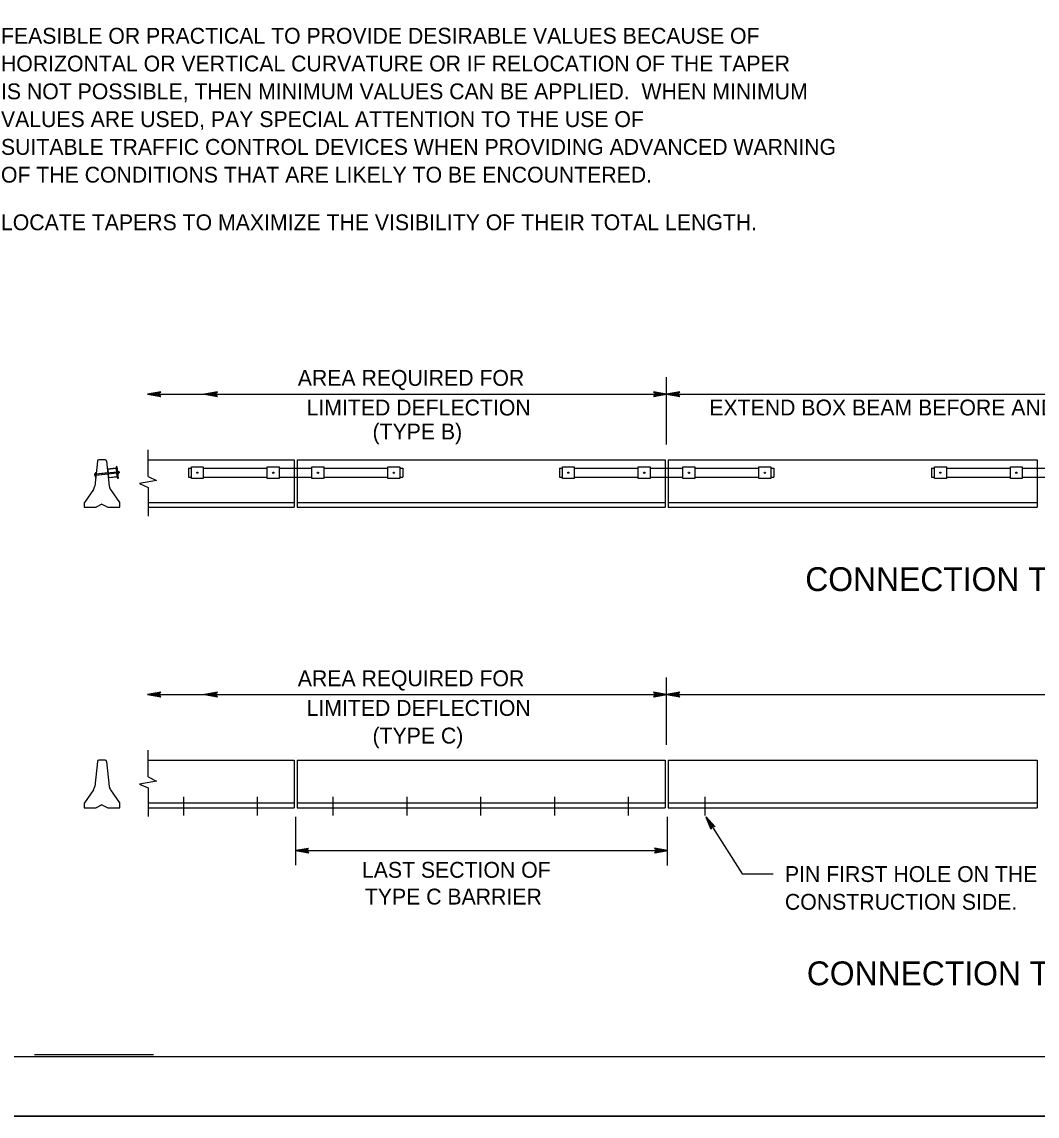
# Model space of a CAD drawing. Extents: x 499909 to 500993, y 502505 to 503165.
# Drawn here: x 500041.5 to 500297.3, y 502505 to 502780.7 of the extents above; entities that cross this region are included whole.
import ezdxf

# ---------------------------------------------------------------- set-up
doc = ezdxf.new("R2010")
doc.units = 0
for name, color, linetype in [('1', 7, 'Continuous'), ('24', 7, 'Continuous'), ('3', 7, 'Continuous'), ('41', 7, 'Continuous'), ('5', 7, 'Continuous')]:
    doc.layers.add(name, color=color, linetype=linetype)

msp = doc.modelspace()

# ---------------------------------------------------------------- linework, layer by layer
at = {"layer": '1'}
for p, q in [((500000, 502520), (500990, 502520)), ((500074.65, 502520.47), (500044.67, 502520.47)), ((500993, 502505), (499944.83, 502505))]:
    msp.add_line(p, q, dxfattribs=at)
at = {"layer": '24'}
for points in [[(500073.16, 502686.89), (500076.48, 502686.3), (500075.69, 502686.89), (500076.46, 502687.47), (500073.16, 502686.89), (500073.38, 502686.9), (500076.39, 502686.34), (500075.63, 502686.9), (500076.33, 502687.42), (500073.5, 502686.91), (500073.61, 502686.89), (500076.19, 502686.43), (500075.61, 502686.9), (500076.2, 502687.35), (500073.66, 502686.89), (500073.77, 502686.91), (500076.02, 502686.5), (500075.59, 502686.89), (500076.03, 502687.29), (500074.09, 502686.91), (500074.28, 502686.91), (500075.86, 502686.58), (500075.55, 502686.88), (500075.88, 502687.21), (500074.31, 502686.89), (500074.49, 502686.88), (500075.68, 502686.68), (500075.45, 502686.91), (500075.69, 502687.13), (500074.65, 502686.89), (500074.82, 502686.87), (500075.53, 502686.74), (500075.41, 502686.9), (500075.61, 502687.07), (500074.91, 502686.89), (500075.37, 502686.78), (500075.3, 502686.91), (500075.51, 502687.03), (500075.02, 502686.91), (500075.33, 502686.83), (500075.2, 502686.93), (500075.35, 502686.99), (500075.2, 502686.9), (500075.28, 502686.88)], [(500087.47, 502686.89), (500090.79, 502686.3), (500090, 502686.89), (500090.77, 502687.47), (500087.47, 502686.89), (500087.69, 502686.9), (500090.7, 502686.34), (500089.93, 502686.9), (500090.64, 502687.42), (500087.8, 502686.91), (500087.92, 502686.89), (500090.49, 502686.43), (500089.92, 502686.9), (500090.51, 502687.35), (500087.97, 502686.89), (500088.08, 502686.91), (500090.33, 502686.5), (500089.89, 502686.89), (500090.34, 502687.29), (500088.4, 502686.91), (500088.59, 502686.91), (500090.16, 502686.58), (500089.86, 502686.88), (500090.19, 502687.21), (500088.62, 502686.89), (500088.8, 502686.88), (500089.98, 502686.68), (500089.76, 502686.91), (500090, 502687.13), (500088.96, 502686.89), (500089.13, 502686.87), (500089.84, 502686.74), (500089.72, 502686.9), (500089.92, 502687.07), (500089.21, 502686.89), (500089.68, 502686.78), (500089.61, 502686.91), (500089.82, 502687.03), (500089.33, 502686.91), (500089.64, 502686.83), (500089.51, 502686.93), (500089.65, 502686.99), (500089.51, 502686.9), (500089.58, 502686.88)], [(500203.94, 502686.89), (500200.62, 502687.48), (500201.41, 502686.89), (500200.63, 502686.31), (500203.94, 502686.89), (500203.72, 502686.88), (500200.71, 502687.43), (500201.47, 502686.88), (500200.77, 502686.36), (500203.6, 502686.87), (500203.49, 502686.89), (500200.91, 502687.35), (500201.49, 502686.88), (500200.89, 502686.43), (500203.44, 502686.89), (500203.33, 502686.87), (500201.07, 502687.28), (500201.51, 502686.89), (500201.07, 502686.48), (500203.01, 502686.87), (500202.82, 502686.87), (500201.24, 502687.2), (500201.55, 502686.9), (500201.22, 502686.57), (500202.79, 502686.89), (500202.61, 502686.9), (500201.42, 502687.1), (500201.65, 502686.87), (500201.4, 502686.64), (500202.45, 502686.89), (500202.28, 502686.91), (500201.57, 502687.04), (500201.68, 502686.88), (500201.49, 502686.7), (500202.19, 502686.89), (500201.73, 502687), (500201.79, 502686.87), (500201.59, 502686.75), (500202.08, 502686.87), (500201.77, 502686.95), (500201.9, 502686.85), (500201.75, 502686.79), (500201.9, 502686.88), (500201.82, 502686.9)], [(500203.94, 502686.89), (500207.26, 502686.3), (500206.47, 502686.89), (500207.25, 502687.47), (500203.94, 502686.89), (500204.16, 502686.9), (500207.17, 502686.34), (500206.41, 502686.9), (500207.11, 502687.42), (500204.28, 502686.91), (500204.39, 502686.89), (500206.97, 502686.43), (500206.39, 502686.9), (500206.99, 502687.35), (500204.44, 502686.89), (500204.55, 502686.91), (500206.81, 502686.5), (500206.37, 502686.89), (500206.82, 502687.29), (500204.87, 502686.91), (500205.06, 502686.91), (500206.64, 502686.58), (500206.33, 502686.88), (500206.66, 502687.21), (500205.09, 502686.89), (500205.27, 502686.88), (500206.46, 502686.68), (500206.23, 502686.91), (500206.48, 502687.13), (500205.43, 502686.89), (500205.6, 502686.87), (500206.31, 502686.74), (500206.2, 502686.9), (500206.39, 502687.07), (500205.69, 502686.89), (500206.15, 502686.78), (500206.09, 502686.91), (500206.29, 502687.03), (500205.81, 502686.91), (500206.11, 502686.83), (500205.98, 502686.93), (500206.13, 502686.99), (500205.98, 502686.9), (500206.06, 502686.88)], [(500073.16, 502611.2), (500076.48, 502610.61), (500075.69, 502611.2), (500076.46, 502611.78), (500073.16, 502611.2), (500073.38, 502611.21), (500076.39, 502610.66), (500075.63, 502611.21), (500076.33, 502611.73), (500073.5, 502611.22), (500073.61, 502611.2), (500076.19, 502610.74), (500075.61, 502611.21), (500076.2, 502611.66), (500073.66, 502611.2), (500073.77, 502611.22), (500076.02, 502610.81), (500075.59, 502611.2), (500076.03, 502611.61), (500074.09, 502611.22), (500074.28, 502611.22), (500075.86, 502610.89), (500075.55, 502611.19), (500075.88, 502611.52), (500074.31, 502611.2), (500074.49, 502611.19), (500075.68, 502610.99), (500075.45, 502611.22), (500075.69, 502611.44), (500074.65, 502611.2), (500074.82, 502611.18), (500075.53, 502611.05), (500075.41, 502611.21), (500075.61, 502611.38), (500074.91, 502611.2), (500075.37, 502611.09), (500075.3, 502611.22), (500075.51, 502611.34), (500075.02, 502611.22), (500075.33, 502611.14), (500075.2, 502611.24), (500075.35, 502611.3), (500075.2, 502611.21), (500075.28, 502611.19)], [(500087.47, 502611.2), (500090.79, 502610.61), (500090, 502611.2), (500090.77, 502611.78), (500087.47, 502611.2), (500087.69, 502611.21), (500090.7, 502610.66), (500089.93, 502611.21), (500090.64, 502611.73), (500087.8, 502611.22), (500087.92, 502611.2), (500090.49, 502610.74), (500089.92, 502611.21), (500090.51, 502611.66), (500087.97, 502611.2), (500088.08, 502611.22), (500090.33, 502610.81), (500089.89, 502611.2), (500090.34, 502611.61), (500088.4, 502611.22), (500088.59, 502611.22), (500090.16, 502610.89), (500089.86, 502611.19), (500090.19, 502611.52), (500088.62, 502611.2), (500088.8, 502611.19), (500089.98, 502610.99), (500089.76, 502611.22), (500090, 502611.44), (500088.96, 502611.2), (500089.13, 502611.18), (500089.84, 502611.05), (500089.72, 502611.21), (500089.92, 502611.38), (500089.21, 502611.2), (500089.68, 502611.09), (500089.61, 502611.22), (500089.82, 502611.34), (500089.33, 502611.22), (500089.64, 502611.14), (500089.51, 502611.24), (500089.65, 502611.3), (500089.51, 502611.21), (500089.58, 502611.19)], [(500203.94, 502611.2), (500200.62, 502611.79), (500201.41, 502611.2), (500200.63, 502610.62), (500203.94, 502611.2), (500203.72, 502611.19), (500200.71, 502611.74), (500201.47, 502611.19), (500200.77, 502610.67), (500203.6, 502611.18), (500203.49, 502611.2), (500200.91, 502611.66), (500201.49, 502611.19), (500200.89, 502610.74), (500203.44, 502611.2), (500203.33, 502611.18), (500201.07, 502611.59), (500201.51, 502611.2), (500201.07, 502610.8), (500203.01, 502611.18), (500202.82, 502611.18), (500201.24, 502611.51), (500201.55, 502611.21), (500201.22, 502610.88), (500202.79, 502611.2), (500202.61, 502611.21), (500201.42, 502611.41), (500201.65, 502611.18), (500201.4, 502610.96), (500202.45, 502611.2), (500202.28, 502611.22), (500201.57, 502611.35), (500201.68, 502611.19), (500201.49, 502611.02), (500202.19, 502611.2), (500201.73, 502611.31), (500201.79, 502611.18), (500201.59, 502611.06), (500202.08, 502611.18), (500201.77, 502611.26), (500201.9, 502611.16), (500201.75, 502611.1), (500201.9, 502611.19), (500201.82, 502611.21)], [(500203.94, 502611.2), (500207.26, 502610.61), (500206.47, 502611.2), (500207.25, 502611.78), (500203.94, 502611.2), (500204.16, 502611.21), (500207.17, 502610.66), (500206.41, 502611.21), (500207.11, 502611.73), (500204.28, 502611.22), (500204.39, 502611.2), (500206.97, 502610.74), (500206.39, 502611.21), (500206.99, 502611.66), (500204.44, 502611.2), (500204.55, 502611.22), (500206.81, 502610.81), (500206.37, 502611.2), (500206.82, 502611.61), (500204.87, 502611.22), (500205.06, 502611.22), (500206.64, 502610.89), (500206.33, 502611.19), (500206.66, 502611.52), (500205.09, 502611.2), (500205.27, 502611.19), (500206.46, 502610.99), (500206.23, 502611.22), (500206.48, 502611.44), (500205.43, 502611.2), (500205.6, 502611.18), (500206.31, 502611.05), (500206.2, 502611.21), (500206.39, 502611.38), (500205.69, 502611.2), (500206.15, 502611.09), (500206.09, 502611.22), (500206.29, 502611.34), (500205.81, 502611.22), (500206.11, 502611.14), (500205.98, 502611.24), (500206.13, 502611.3), (500205.98, 502611.21), (500206.06, 502611.19)], [(500213.86, 502580.38), (500216.13, 502577.9), (500215.21, 502578.25), (500215.14, 502577.28), (500213.86, 502580.38), (500213.97, 502580.2), (500216.05, 502577.95), (500215.17, 502578.3), (500215.11, 502577.42), (500214.02, 502580.09), (500214.1, 502580), (500215.87, 502578.07), (500215.17, 502578.31), (500215.1, 502577.57), (500214.13, 502579.96), (500214.17, 502579.86), (500215.72, 502578.18), (500215.16, 502578.34), (500215.06, 502577.74), (500214.34, 502579.59), (500214.44, 502579.43), (500215.56, 502578.27), (500215.15, 502578.37), (500215.05, 502577.92), (500214.47, 502579.41), (500214.58, 502579.27), (500215.39, 502578.37), (500215.07, 502578.44), (500215.01, 502578.11), (500214.66, 502579.12), (500214.76, 502578.99), (500215.26, 502578.46), (500215.06, 502578.48), (500215.02, 502578.22), (500214.79, 502578.91), (500215.14, 502578.58), (500214.99, 502578.56), (500215, 502578.32), (500214.84, 502578.8), (500215.07, 502578.59), (500214.92, 502578.64), (500214.95, 502578.48), (500214.95, 502578.66), (500215, 502578.6)], [(500110.41, 502571.89), (500113.74, 502571.3), (500112.94, 502571.89), (500113.72, 502572.47), (500110.41, 502571.89), (500110.63, 502571.9), (500113.64, 502571.35), (500112.88, 502571.9), (500113.58, 502572.42), (500110.75, 502571.91), (500110.86, 502571.89), (500113.44, 502571.43), (500112.86, 502571.9), (500113.46, 502572.35), (500110.91, 502571.89), (500111.02, 502571.91), (500113.28, 502571.5), (500112.84, 502571.89), (500113.29, 502572.3), (500111.34, 502571.91), (500111.53, 502571.91), (500113.11, 502571.58), (500112.8, 502571.88), (500113.13, 502572.21), (500111.57, 502571.89), (500111.74, 502571.88), (500112.93, 502571.68), (500112.7, 502571.91), (500112.95, 502572.14), (500111.91, 502571.89), (500112.07, 502571.87), (500112.79, 502571.74), (500112.67, 502571.9), (500112.86, 502572.08), (500112.16, 502571.89), (500112.63, 502571.78), (500112.56, 502571.91), (500112.76, 502572.03), (500112.28, 502571.91), (500112.58, 502571.83), (500112.45, 502571.93), (500112.6, 502571.99), (500112.46, 502571.9), (500112.53, 502571.88)], [(500204.19, 502571.89), (500200.87, 502572.48), (500201.66, 502571.89), (500200.89, 502571.31), (500204.19, 502571.89), (500203.97, 502571.88), (500200.96, 502572.43), (500201.72, 502571.88), (500201.02, 502571.36), (500203.85, 502571.87), (500203.74, 502571.89), (500201.16, 502572.35), (500201.74, 502571.88), (500201.15, 502571.43), (500203.69, 502571.89), (500203.58, 502571.87), (500201.33, 502572.28), (500201.77, 502571.89), (500201.32, 502571.49), (500203.26, 502571.87), (500203.07, 502571.87), (500201.49, 502572.2), (500201.8, 502571.9), (500201.47, 502571.57), (500203.04, 502571.89), (500202.86, 502571.9), (500201.67, 502572.1), (500201.9, 502571.87), (500201.66, 502571.65), (500202.7, 502571.89), (500202.53, 502571.91), (500201.82, 502572.04), (500201.94, 502571.88), (500201.74, 502571.71), (500202.44, 502571.89), (500201.98, 502572), (500202.05, 502571.87), (500201.84, 502571.75), (500202.33, 502571.87), (500202.02, 502571.95), (500202.15, 502571.85), (500202, 502571.79), (500202.15, 502571.88), (500202.07, 502571.9)]]:
    msp.add_lwpolyline(points, dxfattribs=at)
at = {"layer": '3'}
for p, q in [((500073.16, 502686.89), (500765.89, 502686.89)), ((500073.26, 502666.2), (500073.26, 502672.89)), ((500060.5, 502670.06), (500059.84, 502663.75)), ((500062.44, 502670.39), (500060.87, 502670.39)), ((500062.82, 502670.06), (500063.48, 502663.75)), ((500073.26, 502670.39), (500110.06, 502670.39)), ((500110.06, 502670.39), (500110.06, 502668.24)), ((500110.82, 502670.39), (500110.82, 502668.24)), ((500110.82, 502670.39), (500203.54, 502670.39)), ((500203.54, 502670.39), (500203.54, 502668.24)), ((500204.29, 502670.39), (500204.29, 502668.24)), ((500204.29, 502670.39), (500297.28, 502670.39)), ((500297.28, 502670.39), (500297.28, 502668.24)), ((500059.87, 502666.9), (500059.94, 502666.23)), ((500060, 502666.71), (500059.89, 502666.7)), ((500059.97, 502666.42), (500059.92, 502666.42)), ((500060.05, 502667.16), (500059.93, 502666.04)), ((500059.93, 502666.04), (500060.07, 502666.02)), ((500065.59, 502667.01), (500059.97, 502666.42)), ((500059.98, 502666.43), (500060.12, 502666.42)), ((500065.56, 502667.29), (500060, 502666.71)), ((500060.01, 502666.76), (500060.15, 502666.74)), ((500060.05, 502667.16), (500060.19, 502667.14)), ((500063.17, 502666.73), (500060.12, 502666.41)), ((500063.13, 502667.06), (500060.15, 502666.75)), ((500063.04, 502667.92), (500063.26, 502665.87)), ((500063.11, 502667.91), (500063.32, 502665.9)), ((500065.18, 502668.24), (500063.12, 502668.03)), ((500065.16, 502668.17), (500063.16, 502667.96)), ((500065.41, 502666), (500063.36, 502665.79)), ((500065.38, 502666.07), (500063.38, 502665.86)), ((500065.21, 502668.13), (500065.42, 502666.12)), ((500065.42, 502668.64), (500065.23, 502668.62)), ((500065.23, 502668.62), (500065.54, 502665.64)), ((500065.42, 502668.64), (500065.73, 502665.66)), ((500065.75, 502667.45), (500065.57, 502667.43)), ((500065.77, 502667.31), (500065.58, 502667.29)), ((500065.8, 502667.03), (500065.61, 502667.01)), ((500065.81, 502666.89), (500065.63, 502666.87)), ((500065.78, 502667.39), (500065.83, 502666.97)), ((500065.98, 502667.34), (500065.79, 502667.32)), ((500066.01, 502667.06), (500065.82, 502667.04)), ((500065.84, 502667.28), (500065.86, 502667.09)), ((500065.89, 502667.33), (500065.91, 502667.05)), ((500065.94, 502667.28), (500065.96, 502667.1)), ((500065.98, 502667.34), (500066.01, 502667.06)), ((500073.26, 502666.2), (500075.37, 502665.12)), ((500083.44, 502668.24), (500083.44, 502665.99)), ((500083.44, 502668.24), (500084.19, 502668.24)), ((500083.44, 502665.99), (500084.19, 502665.99)), ((500087.19, 502668.24), (500103.32, 502668.24)), ((500087.19, 502665.99), (500103.32, 502665.99)), ((500106.31, 502668.24), (500114.57, 502668.24)), ((500106.31, 502665.99), (500114.57, 502665.99)), ((500110.06, 502668.23), (500110.06, 502666)), ((500110.06, 502666), (500110.06, 502658.4)), ((500110.82, 502668.23), (500110.82, 502666)), ((500110.82, 502665.99), (500110.82, 502658.4)), ((500117.56, 502668.24), (500133.69, 502668.24)), ((500117.56, 502665.99), (500133.69, 502665.99)), ((500136.69, 502668.24), (500137.44, 502668.24)), ((500136.69, 502665.99), (500137.44, 502665.99)), ((500137.44, 502668.24), (500137.44, 502665.99)), ((500176.92, 502668.24), (500176.92, 502665.99)), ((500176.92, 502668.24), (500177.67, 502668.24)), ((500176.92, 502665.99), (500177.67, 502665.99)), ((500180.67, 502668.24), (500196.79, 502668.24)), ((500180.67, 502665.99), (500196.79, 502665.99)), ((500199.79, 502668.24), (500208.04, 502668.24)), ((500199.79, 502665.99), (500208.04, 502665.99)), ((500203.54, 502668.23), (500203.54, 502666)), ((500203.54, 502665.99), (500203.54, 502658.4)), ((500204.29, 502668.23), (500204.29, 502666)), ((500204.29, 502668.23), (500204.29, 502666)), ((500204.29, 502665.99), (500204.29, 502658.4)), ((500211.04, 502668.24), (500227.17, 502668.24)), ((500211.04, 502665.99), (500227.17, 502665.99)), ((500230.17, 502668.24), (500230.92, 502668.24)), ((500230.17, 502665.99), (500230.92, 502665.99)), ((500230.92, 502668.24), (500230.92, 502665.99)), ((500270.66, 502668.24), (500270.66, 502665.99)), ((500270.66, 502668.24), (500271.41, 502668.24)), ((500270.66, 502665.99), (500271.41, 502665.99)), ((500274.41, 502668.24), (500290.54, 502668.24)), ((500274.41, 502665.99), (500290.54, 502665.99)), ((500293.54, 502668.24), (500301.79, 502668.24)), ((500293.54, 502665.99), (500301.79, 502665.99)), ((500297.28, 502668.23), (500297.28, 502665.99)), ((500297.28, 502665.99), (500297.28, 502658.4)), ((500065.73, 502665.66), (500065.54, 502665.64)), ((500075.37, 502665.12), (500071.12, 502664.36)), ((500071.12, 502664.36), (500073.26, 502663.41)), ((500073.26, 502663.41), (500073.26, 502656.15)), ((500059.51, 502662.87), (500057.23, 502659.62)), ((500063.81, 502662.87), (500066.09, 502659.62)), ((500057.16, 502659.4), (500057.16, 502658.4)), ((500057.16, 502658.4), (500060.16, 502658.4)), ((500061.66, 502659.15), (500060.16, 502658.4)), ((500061.66, 502659.15), (500063.16, 502658.4)), ((500063.16, 502658.4), (500066.16, 502658.4)), ((500066.16, 502658.4), (500066.16, 502659.4)), ((500073.26, 502659.62), (500110.06, 502659.62)), ((500073.26, 502658.4), (500110.06, 502658.4)), ((500110.79, 502659.62), (500203.54, 502659.62)), ((500110.82, 502658.4), (500203.54, 502658.4)), ((500204.26, 502659.62), (500297.28, 502659.62)), ((500204.29, 502658.4), (500297.28, 502658.4)), ((500073.16, 502611.2), (500484.62, 502611.2)), ((500073.26, 502590.51), (500073.26, 502597.2)), ((500060.5, 502594.37), (500059.84, 502588.06)), ((500062.44, 502594.7), (500060.87, 502594.7)), ((500062.82, 502594.37), (500063.48, 502588.06)), ((500073.26, 502594.7), (500110.06, 502594.7)), ((500110.06, 502594.7), (500110.06, 502592.55)), ((500110.82, 502594.7), (500110.82, 502592.55)), ((500110.82, 502594.7), (500203.54, 502594.7)), ((500203.54, 502594.7), (500203.54, 502590.31)), ((500204.29, 502594.7), (500204.29, 502590.31)), ((500204.29, 502594.7), (500297.28, 502594.7)), ((500297.28, 502594.7), (500297.28, 502590.3)), ((500110.06, 502592.55), (500110.06, 502582.71)), ((500110.82, 502592.55), (500110.82, 502582.71)), ((500075.37, 502589.43), (500071.12, 502588.67)), ((500073.26, 502590.51), (500075.37, 502589.43)), ((500203.54, 502590.31), (500203.54, 502582.71)), ((500204.29, 502590.31), (500204.29, 502582.71)), ((500297.28, 502590.3), (500297.28, 502582.71)), ((500059.51, 502587.18), (500057.23, 502583.93)), ((500063.81, 502587.18), (500066.09, 502583.93)), ((500071.12, 502588.67), (500073.26, 502587.72)), ((500073.26, 502587.72), (500073.26, 502580.46)), ((500057.16, 502583.71), (500057.16, 502582.71)), ((500061.66, 502583.46), (500060.16, 502582.71)), ((500061.66, 502583.46), (500063.16, 502582.71)), ((500066.16, 502582.71), (500066.16, 502583.71)), ((500073.26, 502583.93), (500110.06, 502583.93)), ((500082.16, 502585.47), (500082.16, 502580.76)), ((500100.76, 502585.47), (500100.76, 502580.76)), ((500110.79, 502583.93), (500203.54, 502583.93)), ((500119.85, 502585.47), (500119.85, 502580.76)), ((500138.45, 502585.47), (500138.45, 502580.76)), ((500157.04, 502585.47), (500157.04, 502580.76)), ((500175.64, 502585.47), (500175.64, 502580.76)), ((500194.24, 502585.47), (500194.24, 502580.76)), ((500204.26, 502583.93), (500297.28, 502583.93)), ((500213.59, 502585.47), (500213.59, 502580.76)), ((500057.16, 502582.71), (500060.16, 502582.71)), ((500063.16, 502582.71), (500066.16, 502582.71)), ((500073.26, 502582.71), (500110.06, 502582.71)), ((500110.82, 502582.71), (500203.54, 502582.71)), ((500204.29, 502582.71), (500297.28, 502582.71)), ((500110.41, 502571.89), (500204.19, 502571.89)), ((500222.96, 502566.01), (500230.8, 502566.01))]:
    msp.add_line(p, q, dxfattribs=at)
for points in [[(500084.19, 502668.62), (500087.19, 502668.62), (500087.19, 502665.62), (500084.19, 502665.62)], [(500103.32, 502668.62), (500106.31, 502668.62), (500106.31, 502665.62), (500103.32, 502665.62)], [(500114.57, 502668.62), (500117.56, 502668.62), (500117.56, 502665.62), (500114.57, 502665.62)], [(500133.69, 502668.62), (500136.69, 502668.62), (500136.69, 502665.62), (500133.69, 502665.62)], [(500177.67, 502668.62), (500180.67, 502668.62), (500180.67, 502665.62), (500177.67, 502665.62)], [(500196.79, 502668.62), (500199.79, 502668.62), (500199.79, 502665.62), (500196.79, 502665.62)], [(500208.04, 502668.62), (500211.04, 502668.62), (500211.04, 502665.62), (500208.04, 502665.62)], [(500227.17, 502668.62), (500230.17, 502668.62), (500230.17, 502665.62), (500227.17, 502665.62)], [(500271.41, 502668.62), (500274.41, 502668.62), (500274.41, 502665.62), (500271.41, 502665.62)], [(500290.54, 502668.62), (500293.54, 502668.62), (500293.54, 502665.62), (500290.54, 502665.62)]]:
    msp.add_lwpolyline(points, close=True, dxfattribs=at)
for centre, radius in [((500085.69, 502667.12), 0.141), ((500104.81, 502667.12), 0.164), ((500116.06, 502667.12), 0.164), ((500135.19, 502667.12), 0.164), ((500179.17, 502667.12), 0.141), ((500198.29, 502667.12), 0.164), ((500209.54, 502667.12), 0.164), ((500228.67, 502667.12), 0.164), ((500272.91, 502667.12), 0.141), ((500292.04, 502667.12), 0.164)]:
    msp.add_circle(centre, radius, dxfattribs=at)
for centre, radius, start, end in [((500060.87, 502670.02), 0.375, 90, 174.0136), ((500062.44, 502670.02), 0.375, 5.9864, 90), ((500060.4, 502666.62), 0.6, 152.1575, 219.8428), ((500063.13, 502667.93), 0.0936, 95.9864, 185.9864), ((500063.16, 502667.91), 0.0468, 95.9864, 185.9864), ((500065.17, 502668.12), 0.0468, 5.9864, 95.9864), ((500065.19, 502668.15), 0.0936, 5.9864, 95.9864), ((500065.38, 502666.12), 0.0468, 275.9864, 5.9864), ((500065.4, 502666.1), 0.0936, 275.9864, 5.9864), ((500065.67, 502667.37), 0.121, 150.4975, 221.4763), ((500066.02, 502667.2), 0.452, 167.8349, 204.1389), ((500065.72, 502666.95), 0.121, 150.4975, 221.4763), ((500065.66, 502667.37), 0.121, 330.497, 41.4758), ((500065.36, 502667.13), 0.452, 347.8344, 24.1384), ((500065.71, 502666.95), 0.121, 330.497, 41.4758), ((500057.97, 502663.95), 1.87, 324.969, 354.0136), ((500063.35, 502665.88), 0.0936, 185.9864, 275.9864), ((500063.37, 502665.91), 0.0468, 185.9864, 275.9864), ((500065.34, 502663.95), 1.87, 185.9864, 215.0335), ((500057.53, 502659.4), 0.375, 144.969, 180), ((500065.78, 502659.4), 0.375, 0, 35.0335), ((500060.87, 502594.33), 0.375, 90, 174.0136), ((500062.44, 502594.33), 0.375, 5.9864, 90), ((500057.97, 502588.26), 1.87, 324.969, 354.0136), ((500065.34, 502588.26), 1.87, 185.9864, 215.0335), ((500057.53, 502583.71), 0.375, 144.969, 180), ((500065.78, 502583.71), 0.375, 0, 35.0335)]:
    msp.add_arc(centre, radius, start, end, dxfattribs=at)
at = {"layer": '41'}
msp.add_lwpolyline([(499944.83, 502505), (500993, 502505), (500993, 503165), (499944.83, 503165)], close=True, dxfattribs=at)
at = {"layer": '5'}
for p, q in [((500203.94, 502674.24), (500203.94, 502691.19)), ((500203.94, 502598.55), (500203.94, 502615.5)), ((500110.5, 502568.24), (500110.5, 502580.43)), ((500204.15, 502568.15), (500204.15, 502580.43)), ((500213.89, 502580.33), (500222.96, 502566.01))]:
    msp.add_line(p, q, dxfattribs=at)

# ---------------------------------------------------------------- texts
at = {"layer": '1'}
for s, height, p in [('FEASIBLE OR PRACTICAL TO PROVIDE DESIRABLE VALUES BECAUSE OF', 4, (500036.21, 502775.21)), ('HORIZONTAL OR VERTICAL CURVATURE OR IF RELOCATION OF THE TAPER', 4, (500036.21, 502768.21)), ('IS NOT POSSIBLE, THEN MINIMUM VALUES CAN BE APPLIED.  WHEN MINIMUM', 4, (500036.21, 502761.21)), ('VALUES ARE USED, PAY SPECIAL ATTENTION TO THE USE OF', 4, (500036.21, 502754.21)), ('SUITABLE TRAFFIC CONTROL DEVICES WHEN PROVIDING ADVANCED WARNING', 4, (500036.21, 502747.21)), ('OF THE CONDITIONS THAT ARE LIKELY TO BE ENCOUNTERED.', 4, (500036.21, 502740.21)), ('LOCATE TAPERS TO MAXIMIZE THE VISIBILITY OF THEIR TOTAL LENGTH.', 4, (500036.21, 502728.21)), ('AREA REQUIRED FOR', 4, (500111, 502689.01)), ('LIMITED DEFLECTION', 4, (500113.21, 502681.54)), ('EXTEND BOX BEAM BEFORE AND AFTER LIMITED DEFLECTION AREA', 4, (500214.69, 502681.54)), ('(TYPE B)', 4, (500129.83, 502675.49)), ('CONNECTION TYPE B TRANSITION', 6, (500238.87, 502637.3)), ('AREA REQUIRED FOR', 4, (500111, 502613.32)), ('LIMITED DEFLECTION', 4, (500113.21, 502605.85)), ('(TYPE C)', 4, (500129.83, 502598.88)), ('LAST SECTION OF ', 4, (500127.16, 502565.05)), ('PIN FIRST HOLE ON THE ', 4, (500233.74, 502563.99)), ('TYPE C BARRIER', 4, (500127.9, 502558.31)), ('CONSTRUCTION SIDE.', 4, (500233.74, 502556.99)), ('CONNECTION TYPE C TRANSITION', 6, (500239.26, 502537.98))]:
    msp.add_text(s, height=height, dxfattribs=at).set_placement(p)

doc.saveas('drawing.dxf')
